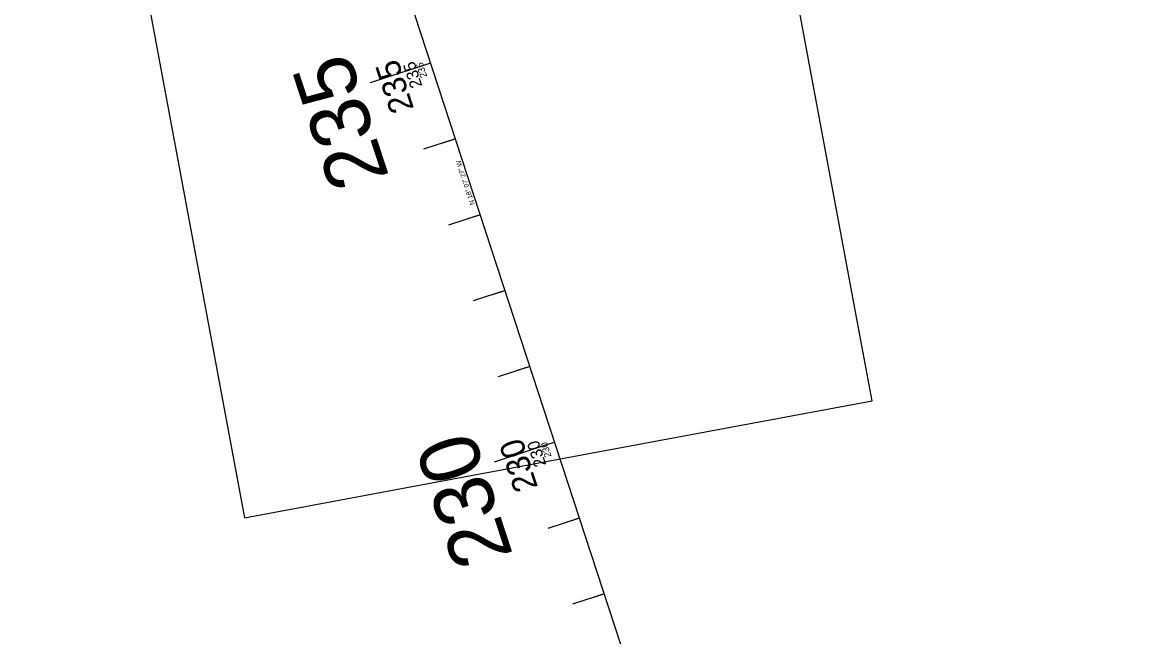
# Model space of a CAD drawing. Extents: x 2358865 to 2362945, y 393485 to 404880.
# Drawn here: x 2358865 to 2360256, y 395523 to 396293 of the extents above; entities that cross this region are included whole.
import ezdxf

# ---------------------------------------------------------------- set-up
doc = ezdxf.new("R2010")
doc.units = 0
for name, color, linetype in [('CL', 7, 'Continuous'), ('Level 21', 7, 'Continuous'), ('Level 25', 7, 'Continuous'), ('Level 30', 7, 'Continuous'), ('Level 39', 7, 'Continuous'), ('Level 41', 7, 'Continuous'), ('Level 63', 7, 'Continuous')]:
    doc.layers.add(name, color=color, linetype=linetype)

msp = doc.modelspace()

# ---------------------------------------------------------------- linework, layer by layer
at = {"layer": 'CL'}
msp.add_line((2360255.9, 393557.3), (2359314.4, 396433.7), dxfattribs=at)
at = {"layer": 'Level 25'}
for p, q in [((2359377.1, 396242.1), (2359369.5, 396239.6)), ((2359408.2, 396147), (2359403.5, 396145.5)), ((2359439.3, 396052), (2359434.6, 396050.4)), ((2359470.4, 395956.9), (2359465.7, 395955.4)), ((2359501.6, 395861.9), (2359496.8, 395860.3)), ((2359532.7, 395766.9), (2359525.1, 395764.4)), ((2359563.8, 395671.8), (2359559, 395670.3)), ((2359594.9, 395576.8), (2359590.1, 395575.2))]:
    msp.add_line(p, q, dxfattribs=at)
at = {"layer": 'Level 30'}
for p, q in [((2359377.1, 396242.1), (2359361.9, 396237.1)), ((2359408.2, 396147), (2359400.2, 396144.4)), ((2359439.3, 396052), (2359431.3, 396049.3)), ((2359470.4, 395956.9), (2359462.4, 395954.3)), ((2359501.6, 395861.9), (2359493.5, 395859.3)), ((2359532.7, 395766.9), (2359517.5, 395761.9)), ((2359563.8, 395671.8), (2359555.7, 395669.2)), ((2359594.9, 395576.8), (2359586.8, 395574.1))]:
    msp.add_line(p, q, dxfattribs=at)
at = {"layer": 'Level 39'}
for p, q in [((2359377.1, 396242.1), (2359346.7, 396232.1)), ((2359408.2, 396147), (2359392.1, 396141.7)), ((2359439.3, 396052), (2359423.2, 396046.7)), ((2359470.4, 395956.9), (2359454.3, 395951.7)), ((2359501.6, 395861.9), (2359485.4, 395856.6)), ((2359532.7, 395766.9), (2359502.3, 395756.9)), ((2359563.8, 395671.8), (2359547.6, 395666.5)), ((2359594.9, 395576.8), (2359578.7, 395571.5))]:
    msp.add_line(p, q, dxfattribs=at)
at = {"layer": 'Level 41'}
for p, q in [((2359377.1, 396242.1), (2359301.1, 396217.2)), ((2359408.2, 396147), (2359368.3, 396134)), ((2359439.3, 396052), (2359399.4, 396038.9)), ((2359470.4, 395956.9), (2359430.5, 395943.9)), ((2359501.6, 395861.9), (2359461.6, 395848.8)), ((2359532.7, 395766.9), (2359456.6, 395742)), ((2359563.8, 395671.8), (2359523.9, 395658.8)), ((2359594.9, 395576.8), (2359555, 395563.7))]:
    msp.add_line(p, q, dxfattribs=at)
at = {"layer": 'Level 63'}
msp.add_lwpolyline([(2359683.4, 397144.2), (2359262, 397221.8), (2359114.5, 397249), (2358865.2, 397167.9), (2359144, 395672.2), (2359537.3, 395745.5), (2359930.5, 395818.9), (2359916.8, 395892.1)], close=True, dxfattribs=at)

# ---------------------------------------------------------------- texts
at = {"layer": 'Level 21'}
msp.add_text('N 18%%d 07\' 27" W', height=6, rotation=108.1241, dxfattribs=at).set_placement((2359432.5, 396065.3))
at = {"layer": 'Level 25'}
for s, p in [('235', (2359372.9, 396225.3)), ('230', (2359528.7, 395749.3))]:
    msp.add_text(s, height=8.75, rotation=108.1241, dxfattribs=at).set_placement(p)
at = {"layer": 'Level 30'}
for s, p in [('235', (2359366.8, 396213.6)), ('230', (2359522.2, 395738.6))]:
    msp.add_text(s, height=15, rotation=108.1241, dxfattribs=at).set_placement(p)
at = {"layer": 'Level 39'}
for s, p in [('235', (2359356.4, 396185.1)), ('230', (2359511.8, 395710.3))]:
    msp.add_text(s, height=30, rotation=108.1241, dxfattribs=at).set_placement(p)
at = {"layer": 'Level 41'}
for s, p in [('235', (2359325.4, 396099.4)), ('230', (2359480.6, 395625.2))]:
    msp.add_text(s, height=75, rotation=108.1241, dxfattribs=at).set_placement(p)

doc.saveas('drawing.dxf')
